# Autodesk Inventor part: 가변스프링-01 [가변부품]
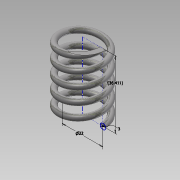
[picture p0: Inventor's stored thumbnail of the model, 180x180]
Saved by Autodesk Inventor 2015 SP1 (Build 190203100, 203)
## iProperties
Created: 2014-12
Part Number: 가변스프링-01 [가변부품]
Material: 강철, 탄소
Document SubType Name: Modeling
Designer: jhkwon
Density: 7.85 g/cm^3
Appearance: 반연마
Mass: 18.8392 g
Surface Area: 32.5593 cm^2
Volume: 2.39989 cm^3
Author: jhkwon
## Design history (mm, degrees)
sketch "스케치1"
  geometry: L1 (0, 0)-(-11, 0); L2 (-11, 0)-(-11, 36.411); L3 (-11, 36.411)-(0, 36.411); L4 (0, 36.411)-(0, 0); C1 r 1.5 at (-11, 0); 1 further point
  constraints: 8 end point, 2 coincident, 2 parallel, 1 centre point, 1 horizontal, 1 perpendicular
  dimensions: "d0" = 3 diameter of C1; "d1" = 22 diameter of L2 L4; "d4" = 36.4112 distance of L1.end L2.end (derived)
feature "코일1" sketch "스케치1" pitch "d5" = 10; turns "d7" = 5; dims "d6" = 36.4112 (= d4), "d8" = 0, angle "d9" = 90 deg, angle "d10" = 90 deg, "d11" = 0, "d12" = 0
sketch "스케치2"
  geometry: L1 (12.5, 0)-(9.5, 0) reference; 1 further point
  constraints: 1 horizontal alignment
extrude "돌출1" cut sketch "스케치2" distance "d13" = 10; taper "d14" = 0 deg
node "작업 평면1"
sketch "스케치3"
  geometry: L1 (0, 0)-(3, 0) reference; 1 further point
  constraints: 1 horizontal alignment
extrude "돌출2" cut sketch "스케치3" distance "d15" = 10; taper "d16" = 0 deg
node "솔리드1"
node "절단 모서리 투영1"
node "절단 모서리 투영2"
